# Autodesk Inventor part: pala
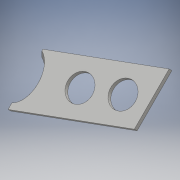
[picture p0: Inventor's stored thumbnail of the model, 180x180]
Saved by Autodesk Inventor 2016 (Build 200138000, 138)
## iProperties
Created: 2016-10
Part Number: pala
Material: Generic
Document SubType Name: Modeling
Designer: Ingenieria
Density: 1 g/cm^3
Appearance: Default
Author: Ingenieria
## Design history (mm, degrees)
workplane "Work Plane1"
sketch "Sketch3"
  geometry: L1 (0, 0)-(191.634, 0); L2 (8.98, 50)-(8.98, -50); L3 (8.98, 50)-(218.798, -16.155); L4 (8.98, 50)-(228.98, 50); L5 (8.98, -50)-(218.798, -116.155); L6 (8.98, -50)-(228.98, -50); L7 (218.798, -116.155)-(218.798, -16.155); 1 further point
  constraints: 14 end point, 3 horizontal, 2 equal length, 1 coincident, 1 vertical
  dimensions: "d12" = 220 distance of L2.start L3.end; "d13" = 17.5 deg angle of L3 L4; "d14" = 220 distance of L2.end L5.end; "d15" = 17.5 deg angle of L5 L6; "d16" = 100 distance between parallel lines of L6 L4; "d17" = 50 distance between parallel lines of L1 L4; "d18" = 218.79771 distance from line of point (0, 0) L7; "d19" = 27.16388 distance from line of L1.end L7
extrude "Extrusion2" new body sketch "Sketch3" stored distance "d20" = 8; taper "d21" = 0 deg
sketch "Sketch4"
  geometry: C1 r 31.75 at (0, 0); 1 further point
  constraints: 1 centre point, 1 coincident
  dimensions: "d22" = 63.5 diameter of C1
extrude "Extrusion3" cut sketch "Sketch4" stored distance "d23" = 100; taper "d24" = 0 deg
workplane "Work Plane2"
sketch "Sketch7" dims "d32" = 50
  geometry: L1 (218.798, 16.155)-(218.798, 116.155) reference; L2 (8.98, -50)-(218.798, 16.155) reference; L3 (218.798, 116.155)-(8.98, 50) reference; L4 (218.798, 66.155)-(31.672, 7.155); L5 (218.798, 66.155)-(372.838, 66.155); A1 r 25 centre (194.955, 58.638) between (218.798, 66.155) and (171.112, 51.12); A2 r 25 centre (171.112, 51.12) between (194.955, 58.638) and (147.269, 43.602); A3 r 25 centre (147.269, 43.602) between (171.112, 51.12) and (123.426, 36.085); A4 r 25 centre (123.426, 36.085) between (147.269, 43.602) and (99.583, 28.567); 6 further points; 1 other entity
  constraints: 8 point on circle, 5 point on line, 4 centre point, 4 end point, 1 coincident, 1 horizontal, 1 midpoint, 8 other
  dimensions: "d31" = 162.5 deg angle of L4 L5
extrude "Extrusion4" cut sketch "Sketch7" stored distance "d33" = 100; taper "d34" = 0 deg
body "Solid2"
other parameters: "d0" = -45 deg, "d30" = 0
